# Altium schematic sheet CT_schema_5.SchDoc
size 611 x 325 mm
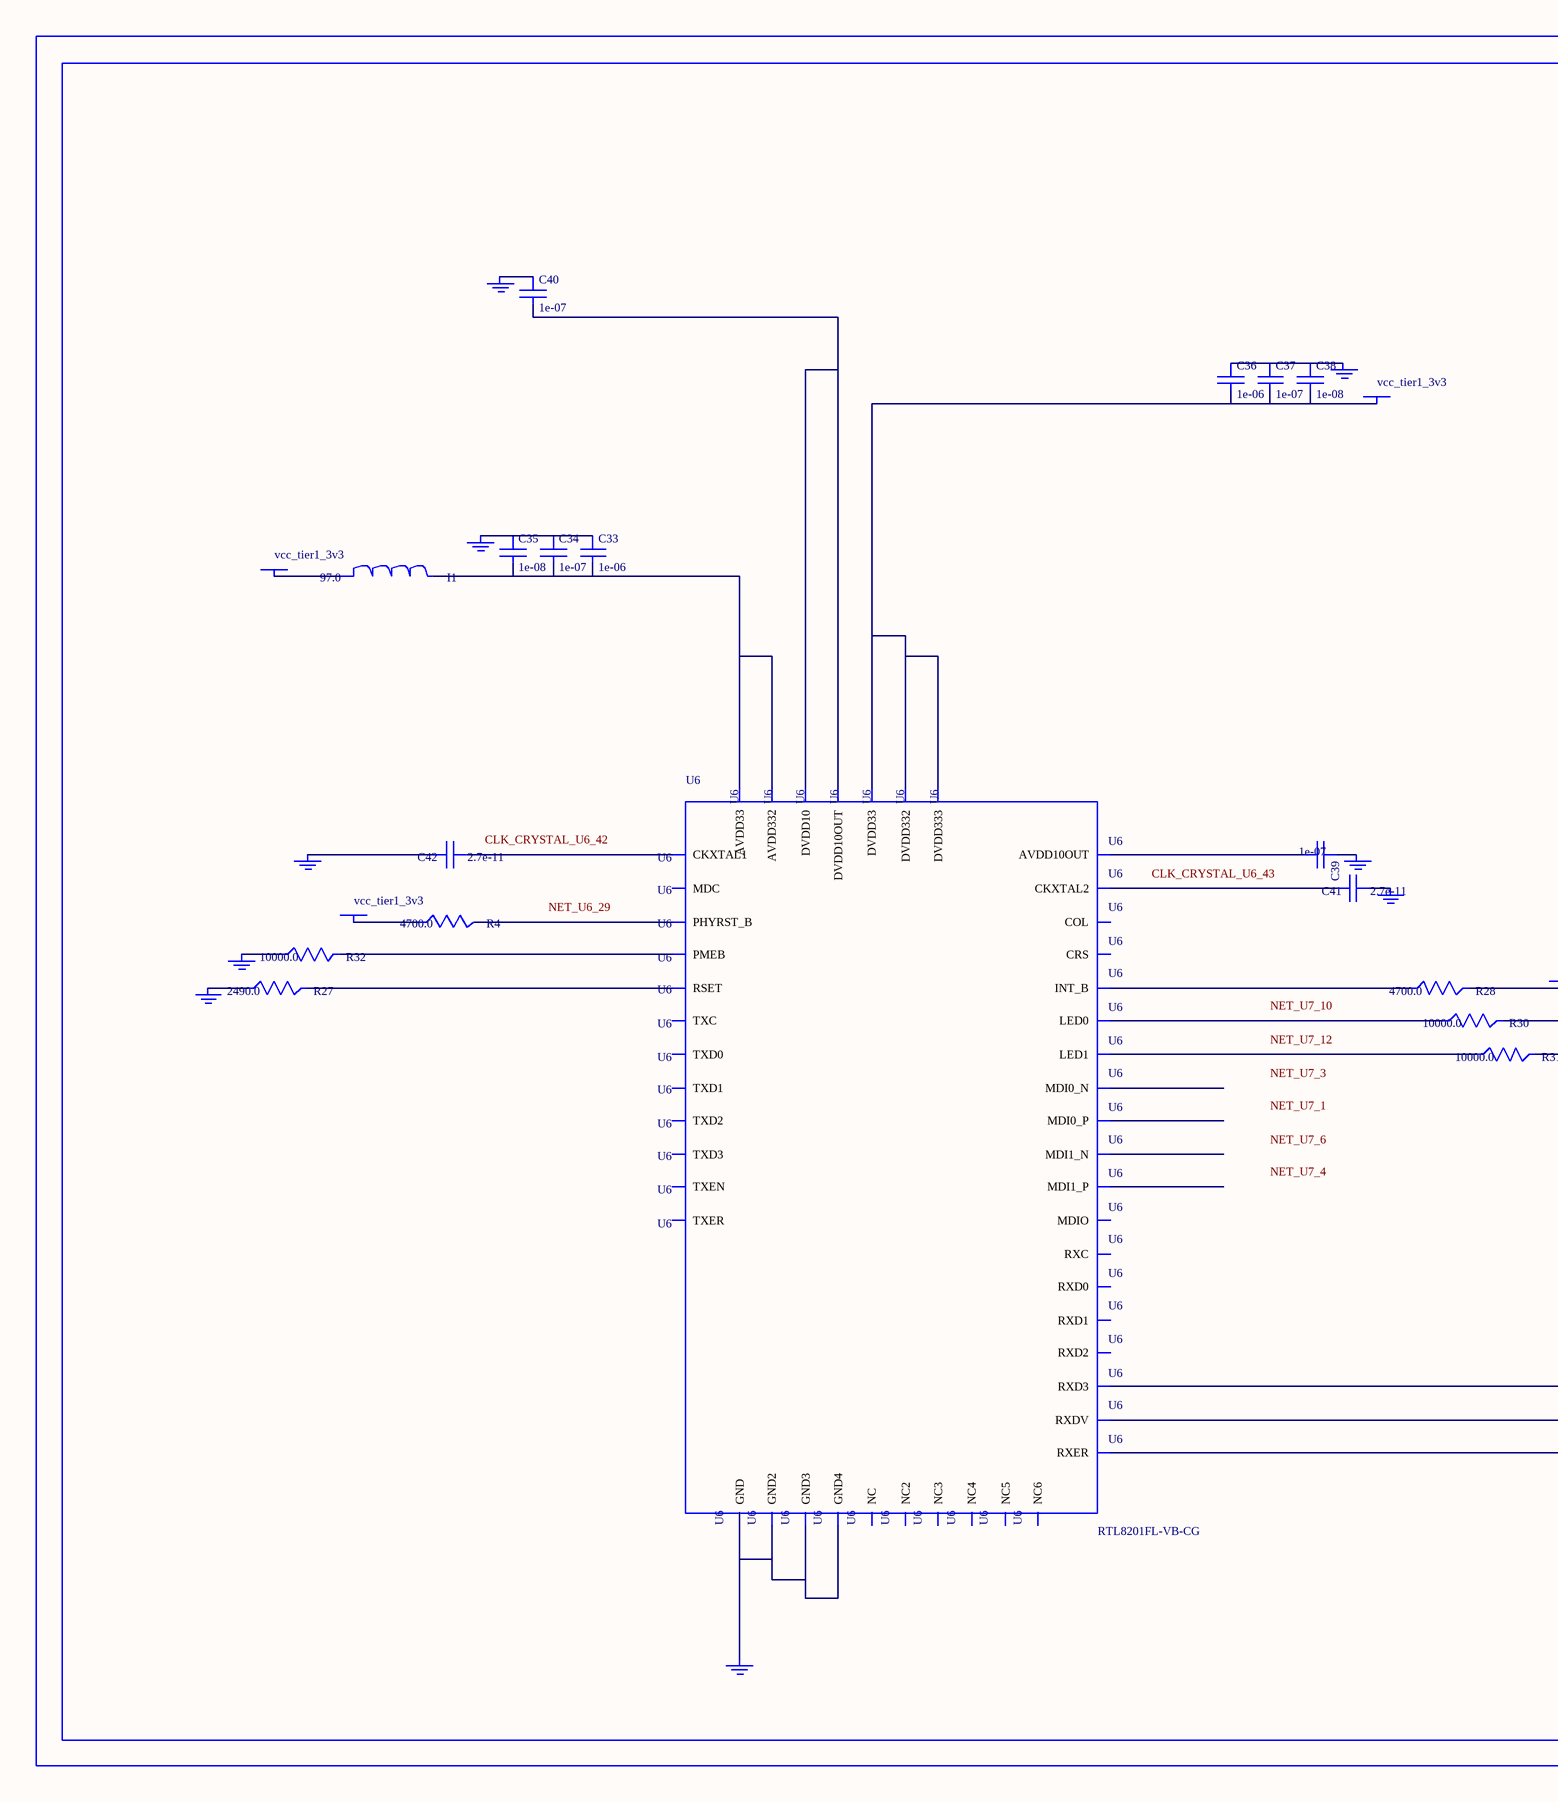
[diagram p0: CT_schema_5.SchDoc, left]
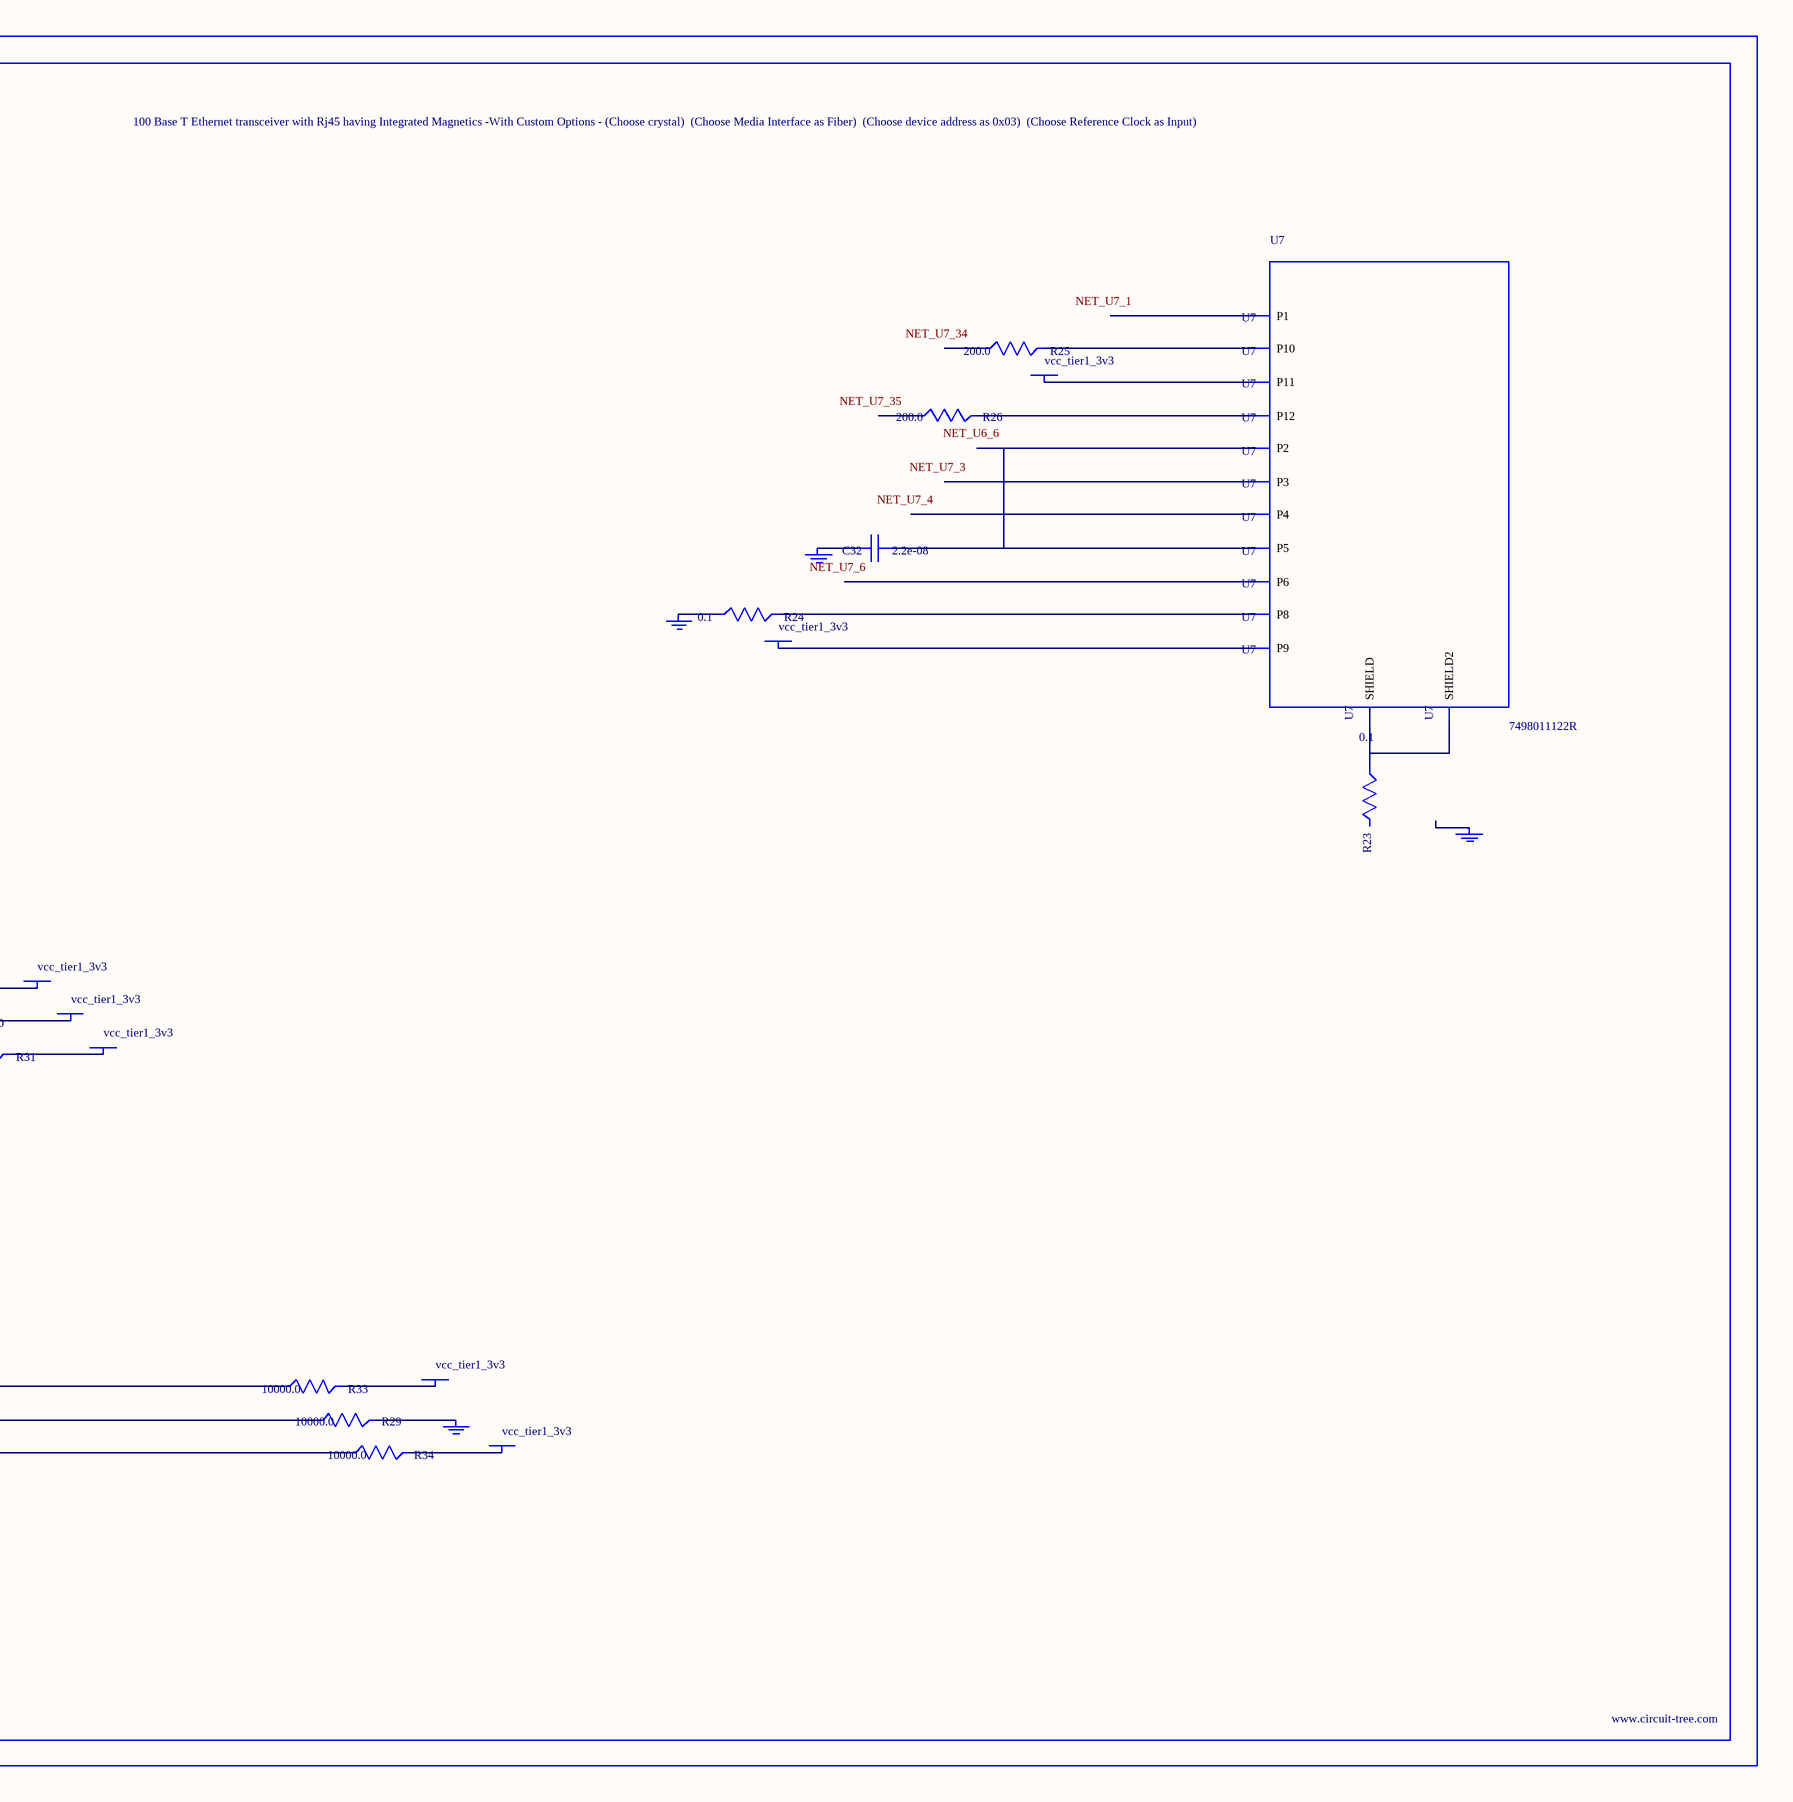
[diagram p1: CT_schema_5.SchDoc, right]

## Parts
BORDER4  (no value)
C32  2.2e-08  [C0402]
C33  1e-06  [C0603]
C34  1e-07  [C0402]
C35  1e-08  [C0402]
C36  1e-06  [C0603]
C37  1e-07  [C0402]
C38  1e-08  [C0402]
C39  1e-07  [C0402]
C40  1e-07  [C0402]
C41  2.7e-11  [C0402]
C42  2.7e-11  [C0402]
GND_INSTANCE_4_0  (no value)
GND_INSTANCE_4_1  (no value)
GND_INSTANCE_4_2  (no value)
GND_INSTANCE_4_3  (no value)
GND_INSTANCE_4_4  (no value)
GND_INSTANCE_4_5  (no value)
GND_INSTANCE_4_6  (no value)
GND_INSTANCE_4_7  (no value)
GND_INSTANCE_4_8  (no value)
GND_INSTANCE_4_9  (no value)
GND_INSTANCE_4_10  (no value)
GND_INSTANCE_4_11  (no value)
GND_INSTANCE_4_12  (no value)
I1  97.0  [R0603]
POWER_INSTANCE_4_0  vcc_tier1_3v3
POWER_INSTANCE_4_1  vcc_tier1_3v3
POWER_INSTANCE_4_2  vcc_tier1_3v3
POWER_INSTANCE_4_3  vcc_tier1_3v3
POWER_INSTANCE_4_4  vcc_tier1_3v3
POWER_INSTANCE_4_5  vcc_tier1_3v3
POWER_INSTANCE_4_6  vcc_tier1_3v3
POWER_INSTANCE_4_7  vcc_tier1_3v3
POWER_INSTANCE_4_8  vcc_tier1_3v3
POWER_INSTANCE_4_9  vcc_tier1_3v3
R4  4700.0  [R0603]
R23  0.1  [R0603]
R24  0.1  [R0603]
R25  200.0  [R0603]
R26  200.0  [R0603]
R27  2490.0  [R0603]
R28  4700.0  [R0603]
R29  10000.0  [R0603]
R30  10000.0  [R0603]
R31  10000.0  [R0603]
R32  10000.0  [R0603]
R33  10000.0  [R0603]
R34  10000.0  [R0603]
U6  RTL8201FL-VB-CG  [RTL8201FL-VB-CG]
U7  7498011122R  [7498011122R]

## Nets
NetC32_1: C32.1 U7.2(P2) U7.5(P5)
NetC32_2: C32.2 GND_INSTANCE_4_10.0(GND)
NetC33_1: C33.1 C34.1 C35.1 GND_INSTANCE_4_0.0(GND)
NetC33_2: C33.2 C34.2 C35.2 I1.2 U6.6(AVDD33) U6.41(AVDD332)
NetC36_1: C36.1 C37.1 C38.1 GND_INSTANCE_4_3.0(GND)
NetC36_2: C36.2 C37.2 C38.2 POWER_INSTANCE_4_1.0(PWR) U6.15(DVDD33) U6.21(DVDD332) U6.37(DVDD333)
NetC39_1: C39.1 GND_INSTANCE_4_8.0(GND)
NetC39_2: C39.2 U6.48(AVDD10OUT)
NetC40_1: C40.1 GND_INSTANCE_4_4.0(GND)
NetC40_2: C40.2 U6.28(DVDD10) U6.40(DVDD10OUT)
NetC41_1: C41.1 GND_INSTANCE_4_6.0(GND)
NetC41_2: C41.2 U6.43(CKXTAL2)
NetC42_1: C42.1 U6.42(CKXTAL1)
NetC42_2: C42.2 GND_INSTANCE_4_5.0(GND)
NetGND_INSTANCE_4_1_0: GND_INSTANCE_4_1.0(GND) R32.1
NetGND_INSTANCE_4_2_0: GND_INSTANCE_4_2.0(GND) R29.2
NetGND_INSTANCE_4_7_0: GND_INSTANCE_4_7.0(GND) R27.1
NetGND_INSTANCE_4_9_0: GND_INSTANCE_4_9.0(GND) U6.7(GND) U6.20(GND2) U6.33(GND3) U6.47(GND4)
NetGND_INSTANCE_4_11_0: GND_INSTANCE_4_11.0(GND) R24.1
NetI1_1: I1.1 POWER_INSTANCE_4_0.0(PWR)
NetPOWER_INSTANCE_4_2_0: POWER_INSTANCE_4_2.0(PWR) R33.2
NetPOWER_INSTANCE_4_3_0: POWER_INSTANCE_4_3.0(PWR) R28.2
NetPOWER_INSTANCE_4_4_0: POWER_INSTANCE_4_4.0(PWR) R30.2
NetPOWER_INSTANCE_4_5_0: POWER_INSTANCE_4_5.0(PWR) R31.2
NetPOWER_INSTANCE_4_6_0: POWER_INSTANCE_4_6.0(PWR) R34.2
NetPOWER_INSTANCE_4_7_0: POWER_INSTANCE_4_7.0(PWR) R4.1
NetPOWER_INSTANCE_4_8_0: POWER_INSTANCE_4_8.0(PWR) U7.9(P9)
NetPOWER_INSTANCE_4_9_0: POWER_INSTANCE_4_9.0(PWR) U7.11(P11)
NetR4_2: R4.2 U6.29(PHYRST_B)
NetR23_1: R23.1 U7.13(SHIELD) U7.14(SHIELD2)
NetR24_2: R24.2 U7.8(P8)
NetR25_2: R25.2 U7.10(P10)
NetR26_2: R26.2 U7.12(P12)
NetR27_2: R27.2 U6.46(RSET)
NetR28_1: R28.1 U6.32(INT_B)
NetR29_1: R29.1 U6.13(RXDV)
NetR30_1: R30.1 U6.34(LED0)
NetR31_1: R31.1 U6.35(LED1)
NetR32_2: R32.2 U6.10(PMEB)
NetR33_1: R33.1 U6.18(RXD3)
NetR34_1: R34.1 U6.39(RXER)

Not connected (* = marked no-connect by the designer): GND_INSTANCE_4_12 0(GND); R23 2; R25 1; R26 1; U6 1(MDI0_P) 2(MDI0_N) 3(NC) 4(MDI1_P) 5(MDI1_N) 8(NC2) 9(NC3) 11(NC4) 12(TXER) 14(RXD0) 16(RXD1) 17(RXD2) 19(RXC) 22(TXC) 23(TXD0) 24(TXD1) 25(TXD2) 26(TXD3) 27(TXEN) 30(MDC) 31(MDIO) 36(CRS) 38(COL) 44(NC5) 45(NC6); U7 1(P1) 3(P3) 4(P4) 6(P6)

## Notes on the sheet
- Labels drawn without touching a wire or pin: CLK_CRYSTAL_U6_42, CLK_CRYSTAL_U6_43, NET_U6_6, NET_U6_29, NET_U7_1, NET_U7_3, NET_U7_4, NET_U7_6, NET_U7_10, NET_U7_12, NET_U7_34, NET_U7_35

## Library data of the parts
BORDER4 = BORDER_PAGE4
C32 = C0402C223K3RAC
C33 C36 = C0603C105K3RACTU
C34 C37 C39 C40 = C0402C104K3RACTU
C35 C38 = C0402C103K3RAC
C41 C42 = C0402C270K3RAC
GND_INSTANCE_4_0-GND_INSTANCE_4_12 = GND
I1 = I1
POWER_INSTANCE_4_0-POWER_INSTANCE_4_9 = PWR
R4 R28 = RC0603JR-074K7L
R23 R24 = ERJ-3RSFR10V
R25 R26 = RC0603JR-07200RL
R27 = ERA-3AED2490V
R29-R34 = RC0603JR-0710KL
